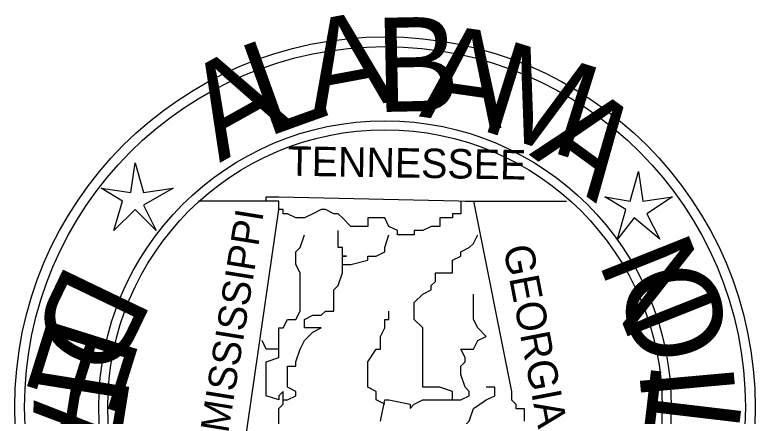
# Model space of a CAD drawing. Extents: x -12822 to 16384, y -6351 to 1913.
# Drawn here: x 54.65 to 100.64, y -6301.31 to -6276.39 of the extents above; entities that cross this region are included whole.
import ezdxf

# ---------------------------------------------------------------- set-up
doc = ezdxf.new("R2010")
doc.units = 0
doc.layers.add('great seal', color=7, linetype='Continuous')

msp = doc.modelspace()

# ---------------------------------------------------------------- linework, layer by layer
at = {"layer": 'great seal'}
for p, q in [((71.058, -6287.947), (66.066, -6287.947)), ((71.058, -6287.947), (66.066, -6287.947)), ((71.058, -6287.947), (66.066, -6287.947)), ((82.62, -6287.947), (88.926, -6287.947)), ((82.62, -6287.947), (88.926, -6287.947)), ((82.62, -6287.947), (88.926, -6287.947)), ((77.627, -6300.56), (77.627, -6300.56)), ((77.627, -6300.56), (77.627, -6300.56)), ((77.627, -6300.56), (77.627, -6300.56)), ((77.627, -6300.56), (77.627, -6300.56)), ((77.627, -6300.56), (77.627, -6300.56)), ((77.627, -6300.56), (77.627, -6300.56))]:
    msp.add_line(p, q, dxfattribs=at)
for points in [[(62.124, -6285.582), (62.65, -6287.422), (64.489, -6287.159), (62.65, -6288.21), (63.438, -6289.787), (62.124, -6288.473), (60.81, -6289.787), (61.336, -6287.947), (60.022, -6287.159), (61.862, -6287.422)], [(62.124, -6285.582), (62.65, -6287.422), (64.489, -6287.159), (62.65, -6288.21), (63.438, -6289.787), (62.124, -6288.473), (60.81, -6289.787), (61.336, -6287.947), (60.022, -6287.159), (61.862, -6287.422)], [(62.124, -6285.582), (62.65, -6287.422), (64.489, -6287.159), (62.65, -6288.21), (63.438, -6289.787), (62.124, -6288.473), (60.81, -6289.787), (61.336, -6287.947), (60.022, -6287.159), (61.862, -6287.422)], [(93.393, -6286.108), (93.656, -6287.947), (95.495, -6287.684), (93.919, -6288.736), (94.707, -6290.312), (93.13, -6288.998), (92.079, -6290.312), (92.605, -6288.473), (91.291, -6287.684), (92.868, -6287.947)], [(93.393, -6286.108), (93.656, -6287.947), (95.495, -6287.684), (93.919, -6288.736), (94.707, -6290.312), (93.13, -6288.998), (92.079, -6290.312), (92.605, -6288.473), (91.291, -6287.684), (92.868, -6287.947)], [(93.393, -6286.108), (93.656, -6287.947), (95.495, -6287.684), (93.919, -6288.736), (94.707, -6290.312), (93.13, -6288.998), (92.079, -6290.312), (92.605, -6288.473), (91.291, -6287.684), (92.868, -6287.947)]]:
    msp.add_lwpolyline(points, close=True, dxfattribs=at)
for points in [[(68.693, -6304.764), (71.058, -6288.473), (71.058, -6287.947), (71.058, -6287.947), (71.058, -6287.947), (70.27, -6287.947), (70.27, -6287.684), (71.058, -6287.684), (83.145, -6287.947), (85.51, -6299.772), (85.51, -6300.297), (85.773, -6300.56), (85.773, -6300.823), (85.773, -6300.823), (86.299, -6300.823), (86.299, -6301.611)], [(68.693, -6304.764), (71.058, -6288.473), (71.058, -6287.947), (71.058, -6287.947), (71.058, -6287.947), (70.27, -6287.947), (70.27, -6287.684), (71.058, -6287.684), (83.145, -6287.947), (85.51, -6299.772), (85.51, -6300.297), (85.773, -6300.56), (85.773, -6300.823), (85.773, -6300.823), (86.299, -6300.823), (86.299, -6301.611)], [(68.693, -6304.764), (71.058, -6288.473), (71.058, -6287.947), (71.058, -6287.947), (71.058, -6287.947), (70.27, -6287.947), (70.27, -6287.684), (71.058, -6287.684), (83.145, -6287.947), (85.51, -6299.772), (85.51, -6300.297), (85.773, -6300.56), (85.773, -6300.823), (85.773, -6300.823), (86.299, -6300.823), (86.299, -6301.611)], [(82.357, -6287.947), (82.357, -6287.947), (82.357, -6287.947), (82.357, -6288.473), (82.357, -6288.736), (82.357, -6288.736), (81.832, -6288.736), (81.832, -6288.736), (81.832, -6288.998), (81.043, -6288.998), (81.043, -6289.524), (80.518, -6289.524), (79.992, -6289.787), (79.729, -6289.787), (79.467, -6289.787), (79.467, -6290.049), (79.204, -6290.049), (79.204, -6290.049), (78.416, -6290.049), (78.416, -6290.049), (78.416, -6289.787), (77.89, -6289.524), (77.627, -6288.998), (77.627, -6288.998), (77.102, -6288.998), (76.576, -6288.998), (76.576, -6289.524), (75.525, -6289.524), (75, -6288.998), (74.737, -6288.736), (74.474, -6288.736), (73.949, -6288.473), (73.686, -6288.473), (73.16, -6288.736), (73.16, -6288.736), (72.635, -6288.998), (72.372, -6288.998), (72.109, -6288.998), (71.584, -6288.736), (71.584, -6288.736), (71.584, -6288.736), (71.321, -6288.736), (71.321, -6288.736), (71.321, -6288.736), (71.321, -6288.473), (71.058, -6288.473), (71.058, -6287.947), (71.058, -6287.947), (71.058, -6287.947)], [(82.357, -6287.947), (82.357, -6287.947), (82.357, -6287.947), (82.357, -6288.473), (82.357, -6288.736), (82.357, -6288.736), (81.832, -6288.736), (81.832, -6288.736), (81.832, -6288.998), (81.043, -6288.998), (81.043, -6289.524), (80.518, -6289.524), (79.992, -6289.787), (79.729, -6289.787), (79.467, -6289.787), (79.467, -6290.049), (79.204, -6290.049), (79.204, -6290.049), (78.416, -6290.049), (78.416, -6290.049), (78.416, -6289.787), (77.89, -6289.524), (77.627, -6288.998), (77.627, -6288.998), (77.102, -6288.998), (76.576, -6288.998), (76.576, -6289.524), (75.525, -6289.524), (75, -6288.998), (74.737, -6288.736), (74.474, -6288.736), (73.949, -6288.473), (73.686, -6288.473), (73.16, -6288.736), (73.16, -6288.736), (72.635, -6288.998), (72.372, -6288.998), (72.109, -6288.998), (71.584, -6288.736), (71.584, -6288.736), (71.584, -6288.736), (71.321, -6288.736), (71.321, -6288.736), (71.321, -6288.736), (71.321, -6288.473), (71.058, -6288.473), (71.058, -6287.947), (71.058, -6287.947), (71.058, -6287.947)], [(82.357, -6287.947), (82.357, -6287.947), (82.357, -6287.947), (82.357, -6288.473), (82.357, -6288.736), (82.357, -6288.736), (81.832, -6288.736), (81.832, -6288.736), (81.832, -6288.998), (81.043, -6288.998), (81.043, -6289.524), (80.518, -6289.524), (79.992, -6289.787), (79.729, -6289.787), (79.467, -6289.787), (79.467, -6290.049), (79.204, -6290.049), (79.204, -6290.049), (78.416, -6290.049), (78.416, -6290.049), (78.416, -6289.787), (77.89, -6289.524), (77.627, -6288.998), (77.627, -6288.998), (77.102, -6288.998), (76.576, -6288.998), (76.576, -6289.524), (75.525, -6289.524), (75, -6288.998), (74.737, -6288.736), (74.474, -6288.736), (73.949, -6288.473), (73.686, -6288.473), (73.16, -6288.736), (73.16, -6288.736), (72.635, -6288.998), (72.372, -6288.998), (72.109, -6288.998), (71.584, -6288.736), (71.584, -6288.736), (71.584, -6288.736), (71.321, -6288.736), (71.321, -6288.736), (71.321, -6288.736), (71.321, -6288.473), (71.058, -6288.473), (71.058, -6287.947), (71.058, -6287.947), (71.058, -6287.947)], [(75, -6291.889), (75, -6291.626), (75, -6291.363), (75.262, -6291.363), (75, -6291.363), (75, -6291.1), (75, -6290.838), (74.737, -6290.838), (74.737, -6290.575), (74.737, -6290.049), (74.737, -6289.787)], [(75, -6291.889), (75, -6291.626), (75, -6291.363), (75.262, -6291.363), (75, -6291.363), (75, -6291.1), (75, -6290.838), (74.737, -6290.838), (74.737, -6290.575), (74.737, -6290.049), (74.737, -6289.787)], [(75, -6291.889), (75, -6291.626), (75, -6291.363), (75.262, -6291.363), (75, -6291.363), (75, -6291.1), (75, -6290.838), (74.737, -6290.838), (74.737, -6290.575), (74.737, -6290.049), (74.737, -6289.787)], [(71.058, -6297.144), (71.058, -6296.618), (71.058, -6296.356), (71.058, -6295.83), (71.321, -6295.83), (71.584, -6295.305), (72.109, -6295.305), (72.372, -6294.779), (72.372, -6293.728), (72.372, -6293.203), (72.372, -6292.94), (72.372, -6292.414), (72.109, -6291.889), (72.109, -6291.363), (72.109, -6291.1), (72.372, -6290.838), (72.635, -6290.049)], [(71.058, -6297.144), (71.058, -6296.618), (71.058, -6296.356), (71.058, -6295.83), (71.321, -6295.83), (71.584, -6295.305), (72.109, -6295.305), (72.372, -6294.779), (72.372, -6293.728), (72.372, -6293.203), (72.372, -6292.94), (72.372, -6292.414), (72.109, -6291.889), (72.109, -6291.363), (72.109, -6291.1), (72.372, -6290.838), (72.635, -6290.049)], [(71.058, -6297.144), (71.058, -6296.618), (71.058, -6296.356), (71.058, -6295.83), (71.321, -6295.83), (71.584, -6295.305), (72.109, -6295.305), (72.372, -6294.779), (72.372, -6293.728), (72.372, -6293.203), (72.372, -6292.94), (72.372, -6292.414), (72.109, -6291.889), (72.109, -6291.363), (72.109, -6291.1), (72.372, -6290.838), (72.635, -6290.049)], [(71.321, -6300.297), (71.321, -6300.297), (71.584, -6300.297), (71.584, -6300.297), (72.109, -6300.034), (72.109, -6299.772), (71.584, -6299.509), (71.584, -6299.509), (71.584, -6298.721), (71.584, -6298.195), (72.109, -6298.195), (72.109, -6297.932), (72.372, -6297.144), (72.635, -6296.618), (73.16, -6296.093), (73.686, -6295.83), (73.16, -6295.83), (72.635, -6295.83), (72.635, -6295.305), (73.16, -6295.042), (73.16, -6295.042), (73.686, -6295.042), (73.949, -6294.779), (73.949, -6294.779), (74.474, -6294.779), (74.474, -6294.254), (74.474, -6293.728), (74.474, -6293.728), (74.474, -6293.465), (74.737, -6293.203), (75, -6292.414), (75, -6292.414), (75, -6291.889), (75.262, -6291.889), (75.525, -6291.889), (75.525, -6291.889), (76.576, -6291.626), (76.576, -6291.363), (77.102, -6291.363), (77.627, -6291.1), (77.627, -6290.838), (77.89, -6290.049)], [(71.321, -6300.297), (71.321, -6300.297), (71.584, -6300.297), (71.584, -6300.297), (72.109, -6300.034), (72.109, -6299.772), (71.584, -6299.509), (71.584, -6299.509), (71.584, -6298.721), (71.584, -6298.195), (72.109, -6298.195), (72.109, -6297.932), (72.372, -6297.144), (72.635, -6296.618), (73.16, -6296.093), (73.686, -6295.83), (73.16, -6295.83), (72.635, -6295.83), (72.635, -6295.305), (73.16, -6295.042), (73.16, -6295.042), (73.686, -6295.042), (73.949, -6294.779), (73.949, -6294.779), (74.474, -6294.779), (74.474, -6294.254), (74.474, -6293.728), (74.474, -6293.728), (74.474, -6293.465), (74.737, -6293.203), (75, -6292.414), (75, -6292.414), (75, -6291.889), (75.262, -6291.889), (75.525, -6291.889), (75.525, -6291.889), (76.576, -6291.626), (76.576, -6291.363), (77.102, -6291.363), (77.627, -6291.1), (77.627, -6290.838), (77.89, -6290.049)], [(71.321, -6300.297), (71.321, -6300.297), (71.584, -6300.297), (71.584, -6300.297), (72.109, -6300.034), (72.109, -6299.772), (71.584, -6299.509), (71.584, -6299.509), (71.584, -6298.721), (71.584, -6298.195), (72.109, -6298.195), (72.109, -6297.932), (72.372, -6297.144), (72.635, -6296.618), (73.16, -6296.093), (73.686, -6295.83), (73.16, -6295.83), (72.635, -6295.83), (72.635, -6295.305), (73.16, -6295.042), (73.16, -6295.042), (73.686, -6295.042), (73.949, -6294.779), (73.949, -6294.779), (74.474, -6294.779), (74.474, -6294.254), (74.474, -6293.728), (74.474, -6293.728), (74.474, -6293.465), (74.737, -6293.203), (75, -6292.414), (75, -6292.414), (75, -6291.889), (75.262, -6291.889), (75.525, -6291.889), (75.525, -6291.889), (76.576, -6291.626), (76.576, -6291.363), (77.102, -6291.363), (77.627, -6291.1), (77.627, -6290.838), (77.89, -6290.049)], [(81.832, -6300.297), (81.832, -6299.772), (81.043, -6299.509), (80.78, -6299.509), (79.992, -6299.509), (79.992, -6298.195), (79.992, -6298.195), (79.992, -6297.932), (79.992, -6297.144), (79.992, -6296.618), (79.992, -6295.83), (79.467, -6295.305), (79.467, -6294.254), (79.992, -6293.728), (80.518, -6293.465), (80.518, -6293.203), (80.78, -6292.94), (80.78, -6292.414), (81.832, -6292.414), (81.832, -6291.889), (81.832, -6291.626), (82.357, -6291.363), (82.357, -6291.1), (82.883, -6290.838), (83.145, -6290.575), (83.408, -6290.049)], [(81.832, -6300.297), (81.832, -6299.772), (81.043, -6299.509), (80.78, -6299.509), (79.992, -6299.509), (79.992, -6298.195), (79.992, -6298.195), (79.992, -6297.932), (79.992, -6297.144), (79.992, -6296.618), (79.992, -6295.83), (79.467, -6295.305), (79.467, -6294.254), (79.992, -6293.728), (80.518, -6293.465), (80.518, -6293.203), (80.78, -6292.94), (80.78, -6292.414), (81.832, -6292.414), (81.832, -6291.889), (81.832, -6291.626), (82.357, -6291.363), (82.357, -6291.1), (82.883, -6290.838), (83.145, -6290.575), (83.408, -6290.049)], [(81.832, -6300.297), (81.832, -6299.772), (81.043, -6299.509), (80.78, -6299.509), (79.992, -6299.509), (79.992, -6298.195), (79.992, -6298.195), (79.992, -6297.932), (79.992, -6297.144), (79.992, -6296.618), (79.992, -6295.83), (79.467, -6295.305), (79.467, -6294.254), (79.992, -6293.728), (80.518, -6293.465), (80.518, -6293.203), (80.78, -6292.94), (80.78, -6292.414), (81.832, -6292.414), (81.832, -6291.889), (81.832, -6291.626), (82.357, -6291.363), (82.357, -6291.1), (82.883, -6290.838), (83.145, -6290.575), (83.408, -6290.049)], [(77.365, -6301.611), (77.627, -6300.297), (77.89, -6300.297), (79.204, -6300.56), (79.204, -6300.823), (79.467, -6300.56), (79.992, -6300.297), (80.78, -6300.297), (81.832, -6300.297), (82.357, -6300.297), (82.883, -6300.034), (82.883, -6299.772), (82.62, -6299.509), (82.62, -6299.509), (82.357, -6298.721), (82.357, -6298.195), (82.62, -6297.932), (82.62, -6297.669), (82.357, -6297.144), (83.145, -6297.144), (83.408, -6296.618), (83.934, -6296.356), (83.408, -6295.83), (83.408, -6295.83), (83.145, -6295.305), (83.145, -6294.779), (83.145, -6293.728)], [(77.365, -6301.611), (77.627, -6300.297), (77.89, -6300.297), (79.204, -6300.56), (79.204, -6300.823), (79.467, -6300.56), (79.992, -6300.297), (80.78, -6300.297), (81.832, -6300.297), (82.357, -6300.297), (82.883, -6300.034), (82.883, -6299.772), (82.62, -6299.509), (82.62, -6299.509), (82.357, -6298.721), (82.357, -6298.195), (82.62, -6297.932), (82.62, -6297.669), (82.357, -6297.144), (83.145, -6297.144), (83.408, -6296.618), (83.934, -6296.356), (83.408, -6295.83), (83.408, -6295.83), (83.145, -6295.305), (83.145, -6294.779), (83.145, -6293.728)], [(77.365, -6301.611), (77.627, -6300.297), (77.89, -6300.297), (79.204, -6300.56), (79.204, -6300.823), (79.467, -6300.56), (79.992, -6300.297), (80.78, -6300.297), (81.832, -6300.297), (82.357, -6300.297), (82.883, -6300.034), (82.883, -6299.772), (82.62, -6299.509), (82.62, -6299.509), (82.357, -6298.721), (82.357, -6298.195), (82.62, -6297.932), (82.62, -6297.669), (82.357, -6297.144), (83.145, -6297.144), (83.408, -6296.618), (83.934, -6296.356), (83.408, -6295.83), (83.408, -6295.83), (83.145, -6295.305), (83.145, -6294.779), (83.145, -6293.728)], [(77.627, -6300.56), (77.102, -6300.297), (77.102, -6300.034), (77.102, -6299.772), (76.576, -6299.509), (76.576, -6298.721), (76.576, -6298.195), (76.576, -6297.932), (76.576, -6297.932), (77.102, -6297.144), (77.365, -6297.144), (77.365, -6296.356), (77.627, -6295.83), (77.627, -6295.83), (77.627, -6295.305), (77.89, -6295.305), (77.89, -6294.779)], [(77.627, -6300.56), (77.102, -6300.297), (77.102, -6300.034), (77.102, -6299.772), (76.576, -6299.509), (76.576, -6298.721), (76.576, -6298.195), (76.576, -6297.932), (76.576, -6297.932), (77.102, -6297.144), (77.365, -6297.144), (77.365, -6296.356), (77.627, -6295.83), (77.627, -6295.83), (77.627, -6295.305), (77.89, -6295.305), (77.89, -6294.779)], [(77.627, -6300.56), (77.102, -6300.297), (77.102, -6300.034), (77.102, -6299.772), (76.576, -6299.509), (76.576, -6298.721), (76.576, -6298.195), (76.576, -6297.932), (76.576, -6297.932), (77.102, -6297.144), (77.365, -6297.144), (77.365, -6296.356), (77.627, -6295.83), (77.627, -6295.83), (77.627, -6295.305), (77.89, -6295.305), (77.89, -6294.779)], [(71.058, -6301.874), (71.058, -6300.823), (71.058, -6300.823), (71.321, -6300.56), (71.321, -6300.297), (71.321, -6299.772), (71.058, -6300.034), (71.058, -6300.297), (70.27, -6300.034), (70.27, -6299.772), (70.27, -6299.509), (70.27, -6299.509), (70.27, -6298.195), (70.27, -6298.195), (70.27, -6297.932), (71.058, -6297.669), (71.058, -6297.144), (70.27, -6297.144), (70.007, -6296.618), (70.007, -6296.618)], [(71.058, -6301.874), (71.058, -6300.823), (71.058, -6300.823), (71.321, -6300.56), (71.321, -6300.297), (71.321, -6299.772), (71.058, -6300.034), (71.058, -6300.297), (70.27, -6300.034), (70.27, -6299.772), (70.27, -6299.509), (70.27, -6299.509), (70.27, -6298.195), (70.27, -6298.195), (70.27, -6297.932), (71.058, -6297.669), (71.058, -6297.144), (70.27, -6297.144), (70.007, -6296.618), (70.007, -6296.618)], [(71.058, -6301.874), (71.058, -6300.823), (71.058, -6300.823), (71.321, -6300.56), (71.321, -6300.297), (71.321, -6299.772), (71.058, -6300.034), (71.058, -6300.297), (70.27, -6300.034), (70.27, -6299.772), (70.27, -6299.509), (70.27, -6299.509), (70.27, -6298.195), (70.27, -6298.195), (70.27, -6297.932), (71.058, -6297.669), (71.058, -6297.144), (70.27, -6297.144), (70.007, -6296.618), (70.007, -6296.618)], [(79.204, -6307.392), (79.204, -6307.392), (79.204, -6306.603), (79.467, -6306.341), (79.467, -6306.078), (79.467, -6305.552), (79.729, -6305.552), (79.992, -6305.027), (80.78, -6304.764), (81.043, -6304.239), (81.832, -6304.239), (81.832, -6303.713), (82.357, -6302.662), (82.357, -6302.136), (82.357, -6302.136), (82.357, -6301.874), (82.62, -6301.874), (82.883, -6301.611), (83.145, -6300.823), (83.934, -6300.297), (84.459, -6300.034), (84.459, -6299.772), (84.459, -6299.509), (83.934, -6299.509)], [(79.204, -6307.392), (79.204, -6307.392), (79.204, -6306.603), (79.467, -6306.341), (79.467, -6306.078), (79.467, -6305.552), (79.729, -6305.552), (79.992, -6305.027), (80.78, -6304.764), (81.043, -6304.239), (81.832, -6304.239), (81.832, -6303.713), (82.357, -6302.662), (82.357, -6302.136), (82.357, -6302.136), (82.357, -6301.874), (82.62, -6301.874), (82.883, -6301.611), (83.145, -6300.823), (83.934, -6300.297), (84.459, -6300.034), (84.459, -6299.772), (84.459, -6299.509), (83.934, -6299.509)], [(79.204, -6307.392), (79.204, -6307.392), (79.204, -6306.603), (79.467, -6306.341), (79.467, -6306.078), (79.467, -6305.552), (79.729, -6305.552), (79.992, -6305.027), (80.78, -6304.764), (81.043, -6304.239), (81.832, -6304.239), (81.832, -6303.713), (82.357, -6302.662), (82.357, -6302.136), (82.357, -6302.136), (82.357, -6301.874), (82.62, -6301.874), (82.883, -6301.611), (83.145, -6300.823), (83.934, -6300.297), (84.459, -6300.034), (84.459, -6299.772), (84.459, -6299.509), (83.934, -6299.509)]]:
    msp.add_lwpolyline(points, dxfattribs=at)
for radius in [22.994, 22.994, 22.994, 22.389, 22.389, 22.389, 17.779, 17.779, 17.779, 17.222, 17.222, 17.222]:
    msp.add_circle((77.645, -6300.744), radius, dxfattribs=at)

# ---------------------------------------------------------------- texts
for s, height, rotation, p in [('A', 5.851, 10.4972, (73.16, -6282.692)), ('A', 5.851, 10.4972, (73.16, -6282.692)), ('A', 5.851, 10.4972, (73.16, -6282.692)), ('B', 5.848, 1.1955, (77.102, -6282.429)), ('B', 5.848, 1.1955, (77.102, -6282.429)), ('B', 5.848, 1.1955, (77.102, -6282.429)), ('A', 5.848, 351.8938, (79.729, -6282.692)), ('A', 5.848, 351.8938, (79.729, -6282.692)), ('A', 5.848, 351.8938, (79.729, -6282.692)), ('L', 5.851, 19.7988, (70.27, -6284.006)), ('L', 5.851, 19.7988, (70.27, -6284.006)), ('L', 5.851, 19.7988, (70.27, -6284.006)), ('M', 5.851, 342.5921, (83.408, -6283.48)), ('A', 5.851, 29.1005, (67.38, -6285.582)), ('A', 5.851, 29.1005, (67.38, -6285.582)), ('A', 5.851, 29.1005, (67.38, -6285.582)), ('A', 5.848, 323.9887, (86.561, -6285.057)), ('A', 5.848, 323.9887, (86.561, -6285.057)), ('A', 5.848, 323.9887, (86.561, -6285.057)), ('TENNESSEE', 1.8304, 359.041, (71.584, -6286.371)), ('TENNESSEE', 1.8304, 359.041, (71.584, -6286.371)), ('TENNESSEE', 1.8304, 359.041, (71.584, -6286.371)), ('MISSISSIPPI', 1.75474, 80.8531, (67.905, -6302.399)), ('MISSISSIPPI', 1.75474, 80.8531, (67.905, -6302.399)), ('MISSISSIPPI', 1.75474, 80.8531, (67.905, -6302.399)), ('N', 5.851, 111.721, (98.386, -6294.779)), ('N', 5.851, 111.721, (98.386, -6294.779)), ('N', 5.851, 111.721, (98.386, -6294.779)), ('GEORGIA', 1.8446, 280.9296, (84.985, -6290.838)), ('GEORGIA', 1.8446, 280.9296, (84.985, -6290.838)), ('GEORGIA', 1.8446, 280.9296, (84.985, -6290.838)), ('O', 5.851, 103.4326, (99.174, -6297.144)), ('O', 5.851, 103.4326, (99.174, -6297.144)), ('O', 5.851, 103.4326, (99.174, -6297.144)), ('D', 5.851, 244.3352, (57.92, -6291.626)), ('D', 5.851, 244.3352, (57.92, -6291.626)), ('D', 5.851, 244.3352, (57.92, -6291.626)), ('E', 5.851, 252.6236, (56.869, -6294.779)), ('E', 5.851, 252.6236, (56.869, -6294.779)), ('E', 5.851, 252.6236, (56.869, -6294.779)), ('P', 5.851, 260.912, (56.081, -6297.932)), ('P', 5.851, 260.912, (56.081, -6297.932)), ('P', 5.851, 260.912, (56.081, -6297.932)), ('T', 5.851, 83.2565, (99.437, -6303.713)), ('T', 5.851, 83.2565, (99.437, -6303.713)), ('T', 5.851, 83.2565, (99.437, -6303.713)), ('I', 5.851, 95.1442, (99.437, -6300.034)), ('I', 5.851, 95.1442, (99.437, -6300.034)), ('I', 5.851, 95.1442, (99.437, -6300.034)), ('A', 5.851, 269.2004, (55.818, -6300.297)), ('A', 5.851, 269.2004, (55.818, -6300.297)), ('A', 5.851, 269.2004, (55.818, -6300.297))]:
    msp.add_text(s, height=height, rotation=rotation, dxfattribs=at).set_placement(p)

doc.saveas('drawing.dxf')
